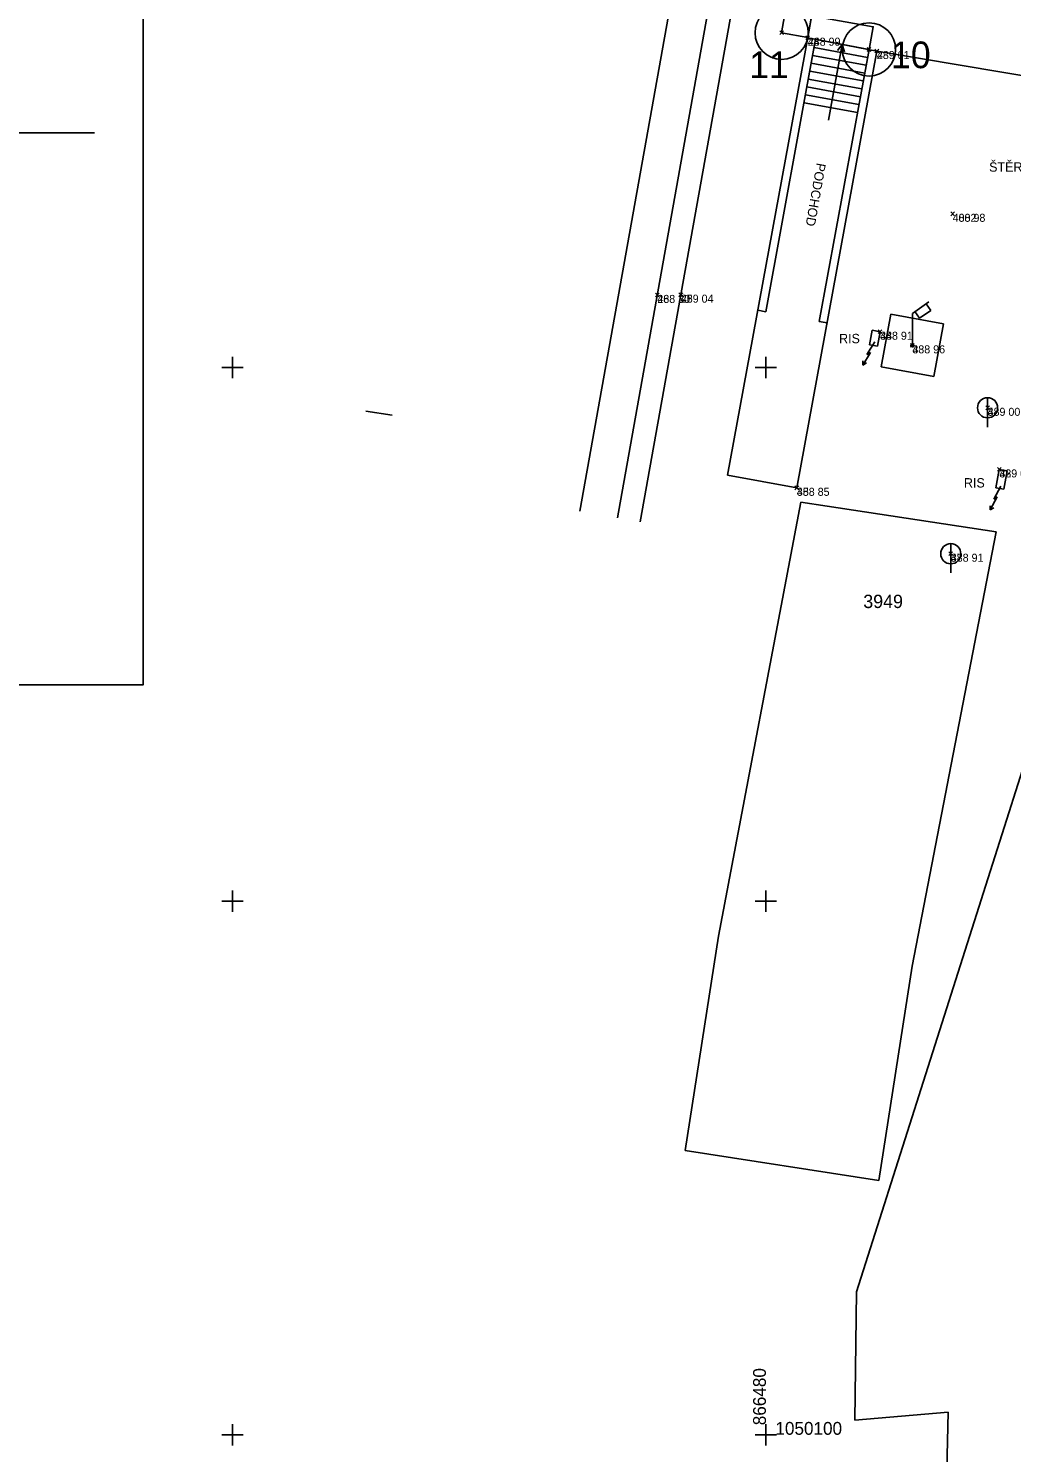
# Model space of a CAD drawing. Extents: x -866624 to -866276, y -1050208 to -1049940.
# Drawn here: x -866507.6 to -866470.8, y -1050100.7 to -1050047.3 of the extents above; entities that cross this region are included whole.
import ezdxf

# ---------------------------------------------------------------- set-up
doc = ezdxf.new("R2010")
doc.units = 0
for name, color, linetype in [('00_BODY VYTYČ', 7, 'Continuous'), ('00_POMOCNÉ KCE', 7, 'Continuous'), ('09_PODLAHY', 7, 'Continuous'), ('_FORMATY', 7, 'Continuous'), ('bod-cislo', 7, 'Continuous'), ('bod-oznac', 7, 'Continuous'), ('bod-vyska', 7, 'Continuous'), ('CTV-SIT', 7, 'Continuous'), ('Default', 7, 'Continuous'), ('EL-ZAR', 7, 'Continuous'), ('HRAN-LIN', 7, 'Continuous'), ('Hranice', 7, 'Continuous'), ('KOLEJ', 7, 'Continuous'), ('Parcela-pozemkova', 7, 'Continuous'), ('POTR-ZAR', 7, 'Continuous'), ('TEXT', 7, 'Continuous'), ('VO', 7, 'Continuous')]:
    doc.layers.add(name, color=color, linetype=linetype)

# ---------------------------------------------------------------- blocks, each defined once
blk = doc.blocks.new('POINT_DISPLAY')
at = {"layer": 'Default'}
for p, q in [((-0.071, 0.071), (0.071, -0.071)), ((0.071, 0.071), (-0.071, -0.071))]:
    blk.add_line(p, q, dxfattribs=at)
blk = doc.blocks.new('200RS')
at = {"layer": 'POTR-ZAR'}
blk.add_line((0, -0.378), (0, 0.721), dxfattribs=at)
blk.add_circle((0, 0), 0.378, dxfattribs=at)
blk = doc.blocks.new('200VO')
at = {"layer": 'VO'}
for p, q in [((0, -0.056), (0, -1.084)), ((-0.247, -0.925), (-0.623, -1.19)), ((-0.09, -1.148), (-0.247, -0.925)), ((-0.466, -1.413), (-0.623, -1.19)), ((0, -1.084), (-0.556, -1.476))]:
    blk.add_line(p, q, dxfattribs=at)
blk.add_circle((0, 0), 0.0557, dxfattribs=at)
blk = doc.blocks.new('CTVSIT')
at = {"layer": 'Default'}
for p, q in [((-2, 0), (2, 0)), ((0, 2), (0, -2))]:
    blk.add_line(p, q, dxfattribs=at)
blk = doc.blocks.new('vytyčení')
at = {"layer": '00_POMOCNÉ KCE'}
for centre in [(-866029.142, -1050084.394), (-866029.271, -1050087.726)]:
    blk.add_circle(centre, 0.998, dxfattribs=at)
at = {"layer": '09_PODLAHY'}
for points in [[(-866030.068, -1050086.709), (-866030.008, -1050084.365), (-866029.142, -1050084.394), (-866029.234, -1050086.729), (-866030.068, -1050086.709)], [(-866076.389, -1050085.553), (-866077.898, -1050085.519), (-866077.927, -1050086.627), (-866076.412, -1050086.552), (-866042.25, -1050087.417), (-866029.271, -1050087.726), (-866029.245, -1050086.729)]]:
    blk.add_lwpolyline(points, close=True, dxfattribs=at)

msp = doc.modelspace()

# ---------------------------------------------------------------- linework, layer by layer
at = {"layer": '00_BODY VYTYČ'}
msp.add_line((-866533.907, -1050051.21), (-866505.162, -1050051.21), dxfattribs=at)
msp.add_lwpolyline([(-866535.574, -1050040.029), (-866503.342, -1050040.029), (-866503.342, -1050071.892), (-866535.574, -1050071.892)], close=True, dxfattribs=at)
at = {"layer": '_FORMATY'}
msp.add_line((-866495.002, -1050061.632), (-866494.013, -1050061.782), dxfattribs=at)
at = {"layer": 'EL-ZAR'}
for p, q in [((-866475.919, -1050059.038), (-866476.215, -1050059.511)), ((-866476.076, -1050059.433), (-866476.372, -1050059.907)), ((-866476.372, -1050059.907), (-866476.363, -1050059.748)), ((-866476.215, -1050059.511), (-866476.076, -1050059.433)), ((-866476.372, -1050059.907), (-866476.233, -1050059.829)), ((-866471.195, -1050064.443), (-866471.458, -1050064.936)), ((-866471.325, -1050064.848), (-866471.588, -1050065.341)), ((-866471.458, -1050064.936), (-866471.325, -1050064.848)), ((-866471.588, -1050065.341), (-866471.589, -1050065.181)), ((-866471.588, -1050065.341), (-866471.454, -1050065.254))]:
    msp.add_line(p, q, dxfattribs=at)
at = {"layer": 'HRAN-LIN'}
for p, q in [((-866472.79, -1049999.16), (-866484.714, -1050065.787)), ((-866478.428, -1050047.629), (-866481.434, -1050064.035)), ((-866478.135, -1050047.697), (-866480.007, -1050057.911)), ((-866475.84, -1050048.14), (-866478.43, -1050047.64)), ((-866476.188, -1050048.377), (-866478.193, -1050048.01)), ((-866477.135, -1050047.89), (-866477.656, -1050050.733)), ((-866477.135, -1050047.89), (-866477.31, -1050048.122)), ((-866477.135, -1050047.89), (-866477.053, -1050048.169)), ((-866475.84, -1050048.14), (-866478.84, -1050064.51)), ((-866476.243, -1050048.672), (-866478.247, -1050048.305)), ((-866476.134, -1050048.082), (-866478.003, -1050058.278)), ((-866475.84, -1050048.14), (-866462.47, -1050050.41)), ((-866476.351, -1050049.262), (-866478.355, -1050048.895)), ((-866476.297, -1050048.967), (-866478.301, -1050048.6)), ((-866476.459, -1050049.852), (-866478.463, -1050049.485)), ((-866476.405, -1050049.557), (-866478.409, -1050049.19)), ((-866476.567, -1050050.443), (-866478.571, -1050050.075)), ((-866476.513, -1050050.148), (-866478.517, -1050049.78)), ((-866480.302, -1050057.857), (-866480.007, -1050057.911)), ((-866475.313, -1050058.006), (-866475.674, -1050059.973)), ((-866475.313, -1050058.006), (-866473.346, -1050058.367)), ((-866478.003, -1050058.278), (-866477.708, -1050058.332)), ((-866476.015, -1050058.606), (-866476.114, -1050059.147)), ((-866475.72, -1050058.66), (-866476.015, -1050058.606)), ((-866475.72, -1050058.66), (-866475.819, -1050059.201)), ((-866473.346, -1050058.367), (-866473.707, -1050060.334)), ((-866475.819, -1050059.201), (-866476.114, -1050059.147)), ((-866475.674, -1050059.973), (-866473.707, -1050060.334)), ((-866471.25, -1050063.82), (-866471.376, -1050064.509)), ((-866470.955, -1050063.874), (-866471.25, -1050063.82)), ((-866470.955, -1050063.874), (-866471.081, -1050064.563)), ((-866478.84, -1050064.51), (-866481.434, -1050064.035)), ((-866471.081, -1050064.563), (-866471.376, -1050064.509))]:
    msp.add_line(p, q, dxfattribs=at)
at = {"layer": 'Hranice'}
for p, q in [((-866466.78, -1050063.73), (-866476.6, -1050094.64)), ((-866481.78, -1050081.31), (-866478.69, -1050065.05)), ((-866477.7, -1050065.2), (-866478.69, -1050065.05)), ((-866471.37, -1050066.16), (-866477.7, -1050065.2)), ((-866471.37, -1050066.16), (-866474.52, -1050082.44)), ((-866481.78, -1050081.31), (-866483.03, -1050089.34)), ((-866475.77, -1050090.47), (-866474.52, -1050082.44)), ((-866483.03, -1050089.34), (-866475.77, -1050090.47)), ((-866476.6, -1050094.64), (-866476.67, -1050099.45)), ((-866476.67, -1050099.45), (-866473.17, -1050099.15)), ((-866473.26, -1050103.09), (-866473.17, -1050099.15))]:
    msp.add_line(p, q, dxfattribs=at)
at = {"layer": 'KOLEJ'}
for p, q in [((-866473.069, -1049987.559), (-866486.976, -1050065.382)), ((-866471.656, -1049987.812), (-866485.563, -1050065.635))]:
    msp.add_line(p, q, dxfattribs=at)

# ---------------------------------------------------------------- block references
at = {"layer": '00_BODY VYTYČ'}
for p in [(-866479.41, -1050047.455), (-866476.134, -1050048.08)]:
    msp.add_blockref('POINT_DISPLAY', p, dxfattribs=at)
at = {"layer": '00_POMOCNÉ KCE', "rotation": -98.59344504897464}
msp.add_blockref('vytyčení', (42415.469, -2063260.675), dxfattribs=at)
at = {"layer": '00_POMOCNÉ KCE'}
for p in [(-866479.41, -1050047.455), (-866476.135, -1050048.083)]:
    msp.add_blockref('POINT_DISPLAY', p, dxfattribs=at)
at = {"layer": 'bod-oznac'}
for p in [(-866478.43, -1050047.64), (-866475.84, -1050048.14), (-866473, -1050054.24), (-866484.07, -1050057.28), (-866483.19, -1050057.27), (-866475.72, -1050058.66), (-866474.51, -1050059.17), (-866471.69, -1050061.51), (-866471.25, -1050063.82), (-866478.84, -1050064.51), (-866473.07, -1050066.98)]:
    msp.add_blockref('POINT_DISPLAY', p, dxfattribs=at)
at = {"layer": 'CTV-SIT', "xscale": 0.19999999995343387, "yscale": 0.19999999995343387}
for p in [(-866500, -1050060), (-866480, -1050060), (-866500, -1050080), (-866480, -1050080), (-866500, -1050100), (-866480, -1050100)]:
    msp.add_blockref('CTVSIT', p, dxfattribs=at)
at = {"layer": 'POTR-ZAR', "rotation": 179.99999999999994}
for p in [(-866471.69, -1050061.51), (-866473.07, -1050066.98)]:
    msp.add_blockref('200RS', p, dxfattribs=at)
at = {"layer": 'VO', "xscale": 1.1025, "yscale": 1.1025, "rotation": 179.99999999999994}
msp.add_blockref('200VO', (-866474.51, -1050059.17), dxfattribs=at)

# ---------------------------------------------------------------- texts
at = {"layer": '00_BODY VYTYČ'}
for s, p in [('10', (-866475.31, -1050048.783)), ('11', (-866480.627, -1050049.156))]:
    msp.add_text(s, height=1, dxfattribs=at).set_placement(p)
at = {"layer": 'bod-cislo'}
for s, p in [('24', (-866478.43, -1050047.94)), ('23', (-866475.84, -1050048.44)), ('4002', (-866473, -1050054.54)), ('26', (-866484.07, -1050057.58)), ('25', (-866483.19, -1050057.57)), ('34', (-866475.72, -1050058.96)), ('33', (-866474.51, -1050059.47)), ('38', (-866471.69, -1050061.81)), ('32', (-866471.25, -1050064.12)), ('35', (-866478.84, -1050064.81)), ('37', (-866473.07, -1050067.28))]:
    msp.add_text(s, height=0.3, dxfattribs=at).set_placement(p)
at = {"layer": 'bod-vyska'}
for s, p in [('488 99', (-866478.43, -1050047.94)), ('489 01', (-866475.84, -1050048.44)), ('488 98', (-866473, -1050054.54)), ('488 30', (-866484.07, -1050057.58)), ('489 04', (-866483.19, -1050057.57)), ('488 91', (-866475.72, -1050058.96)), ('488 96', (-866474.51, -1050059.47)), ('489 00', (-866471.69, -1050061.81)), ('489 02', (-866471.25, -1050064.12)), ('488 85', (-866478.84, -1050064.81)), ('488 91', (-866473.07, -1050067.28))]:
    msp.add_text(s, height=0.3, dxfattribs=at).set_placement(p)
at = {"layer": 'CTV-SIT'}
msp.add_text('  866480', height=0.48, rotation=90, dxfattribs=at).set_placement((-866480, -1050100))
msp.add_text('  1050100', height=0.48, dxfattribs=at).set_placement((-866480, -1050100))
at = {"layer": 'Parcela-pozemkova'}
msp.add_text('3949', height=0.5, dxfattribs=at).set_placement((-866476.35, -1050069.016))
at = {"layer": 'TEXT'}
for s, p in [('ŠTĚRK', (-866471.631, -1050052.662)), ('RIS', (-866477.257, -1050059.09)), ('RIS', (-866472.576, -1050064.498))]:
    msp.add_text(s, height=0.35, dxfattribs=at).set_placement(p)
msp.add_text('PODCHOD', height=0.35, rotation=259.9728, dxfattribs=at).set_placement((-866478.096, -1050052.317))

doc.saveas('drawing.dxf')
